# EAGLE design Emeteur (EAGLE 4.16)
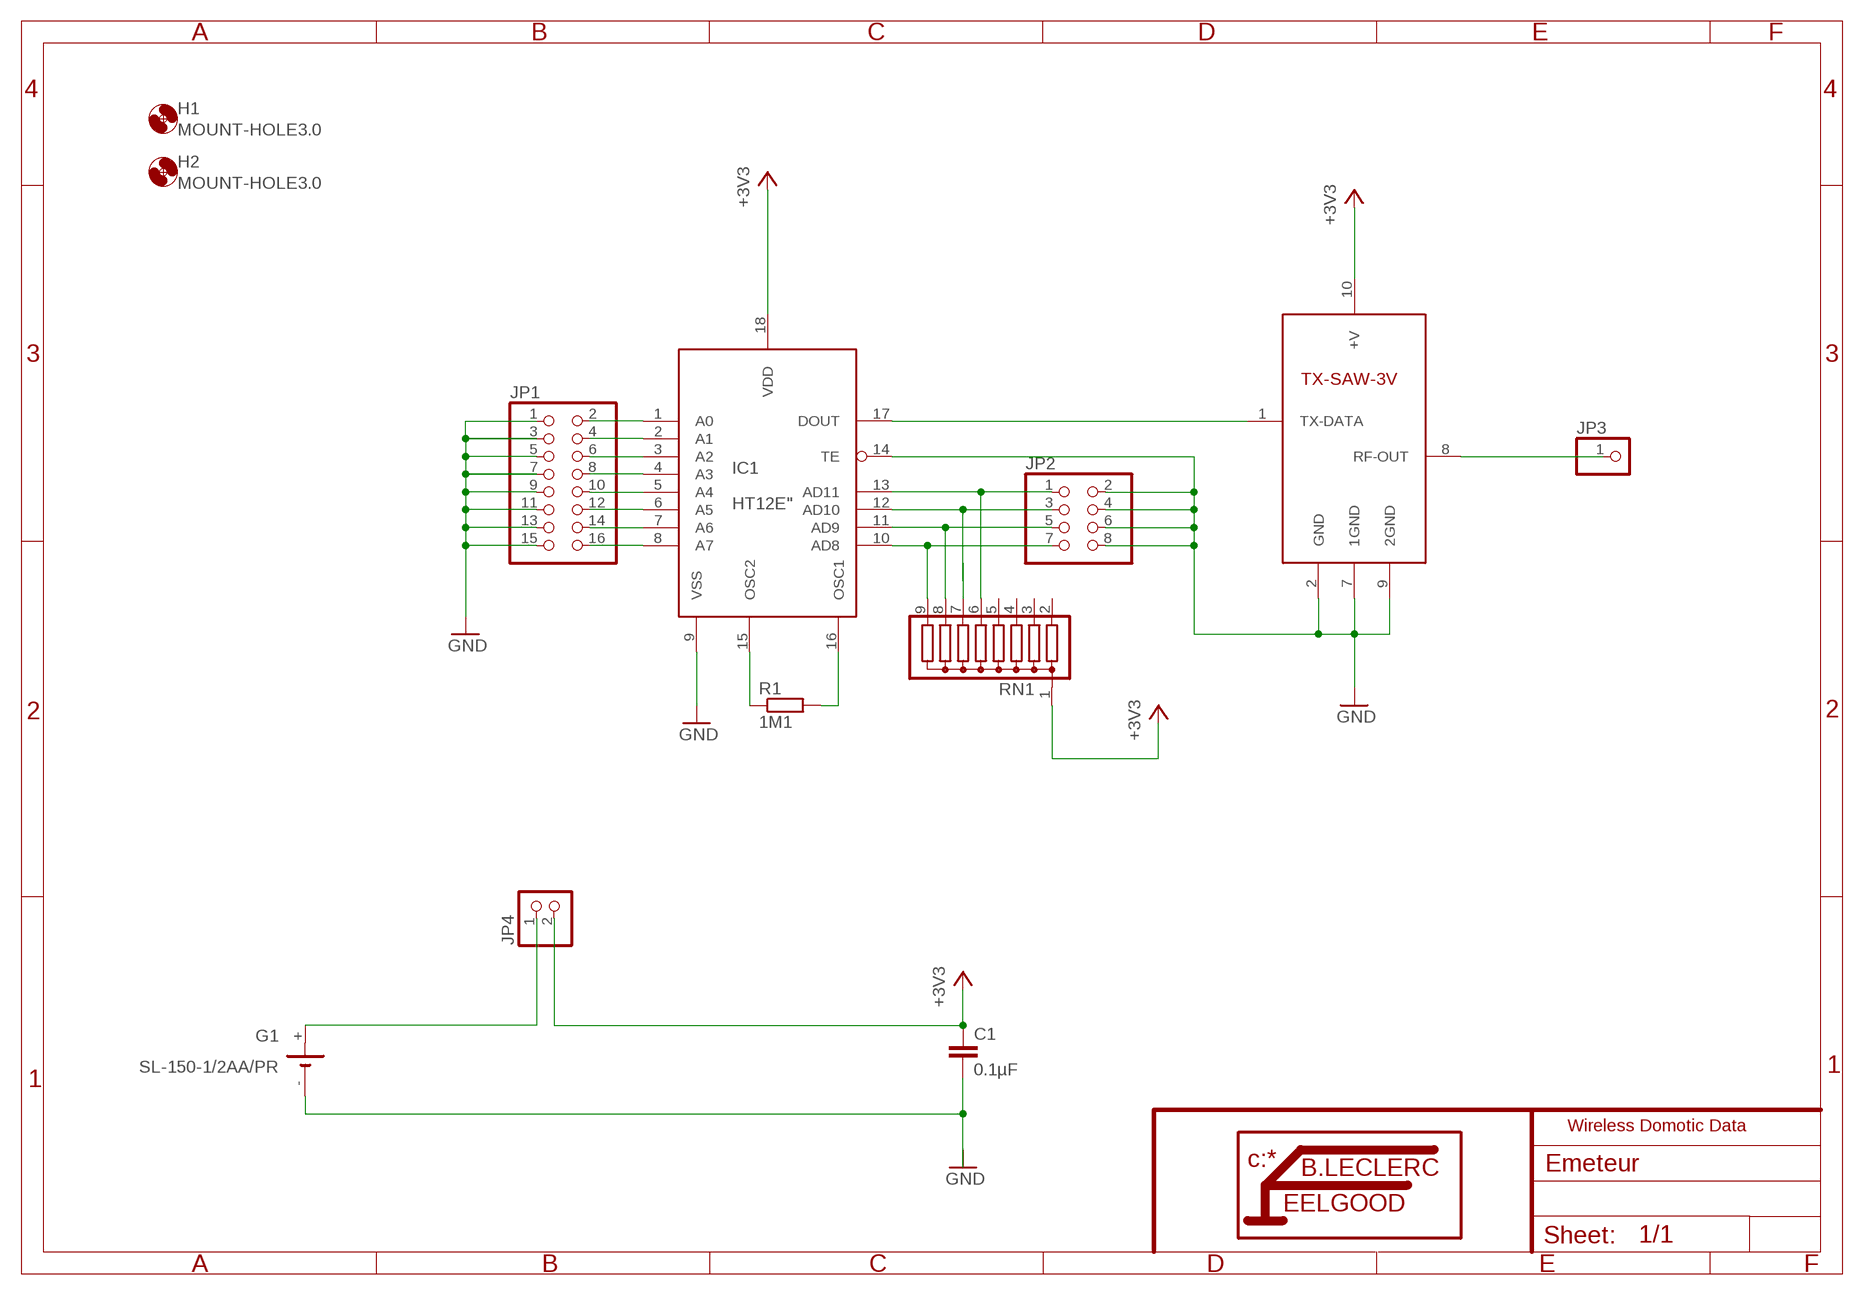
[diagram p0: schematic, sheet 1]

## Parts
C1  0.1µF  C-EU075-032X103  [C075-032X103]
G1  SL-150-1/2AA/PR  [SL-150-1/2AA/PR]
H1  MOUNT-HOLE3.0  [3,0]
H2  MOUNT-HOLE3.0  [3,0]
IC1  HT12E"  [18-DIP-A]
JP1  PINHD-2X8  [2X08]
JP2  PINHD-2X4  [2X04]
JP3  PINHD-1X1  [1X01]
JP4  PINHD-1X2  [1X02]
R1  1M1  R-EU_0207/10  [0207/10]
RN1  G08R  [SIL9]
TX-SAW1  AUREL_TX-SAW-3V  [AUREL_TX-SAW_3V]

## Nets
+3V3: C1.1 IC1.18(VDD) JP4.2 RN1.1 TX-SAW1.10(+V)
GND: C1.2 G1.- IC1.9(VSS) IC1.14(TE) JP1.1 JP1.3 JP1.5 JP1.7 JP1.9 JP1.11 JP1.13 JP1.15 JP2.2 JP2.4 JP2.6 JP2.8 TX-SAW1.2(GND) TX-SAW1.7(1GND) TX-SAW1.9(2GND)
N$1: JP3.1 TX-SAW1.8(RF-OUT)
N$2: IC1.13(AD11) JP2.1 RN1.6
N$3: IC1.17(DOUT) TX-SAW1.1(TX-DATA)
N$4: IC1.12(AD10) JP2.3 RN1.7
N$5: IC1.11(AD9) JP2.5 RN1.8
N$6: IC1.10(AD8) JP2.7 RN1.9
N$7: IC1.15(OSC2) R1.1
N$8: IC1.16(OSC1) R1.2
N$9: IC1.1(A0) JP1.2
N$10: IC1.2(A1) JP1.4
N$11: IC1.3(A2) JP1.6
N$12: IC1.4(A3) JP1.8
N$13: IC1.5(A4) JP1.10
N$14: IC1.6(A5) JP1.12
N$15: IC1.7(A6) JP1.14
N$16: IC1.8(A7) JP1.16
N$18: G1.+ JP4.1
Unconnected: RN1.2 RN1.3 RN1.4 RN1.5

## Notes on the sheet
- Wireless Domotic Data

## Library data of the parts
C1 = rcl:C-EU: CAPACITOR, European symbol
G1 = battery:SL-150-1/2AA/PR: LI BATTERY Sonnenschein
H1 H2 = holes:MOUNT-HOLE: MOUNTING HOLE with drill center marker
IC1 = holtek:HT12E: transmitter = encoder ic
JP1 = pinhead:PINHD-2X8: PIN HEADER
JP2 = pinhead:PINHD-2X4: PIN HEADER
JP3 = pinhead:PINHD-1X1: PIN HEADER
JP4 = pinhead:PINHD-1X2: PIN HEADER
R1 = rcl:R-EU_: RESISTOR, European symbol
RN1 = resistor-sil:G08R: SIL RESISTOR
TX-SAW1 = aurel:AUREL_TX-SAW-3V

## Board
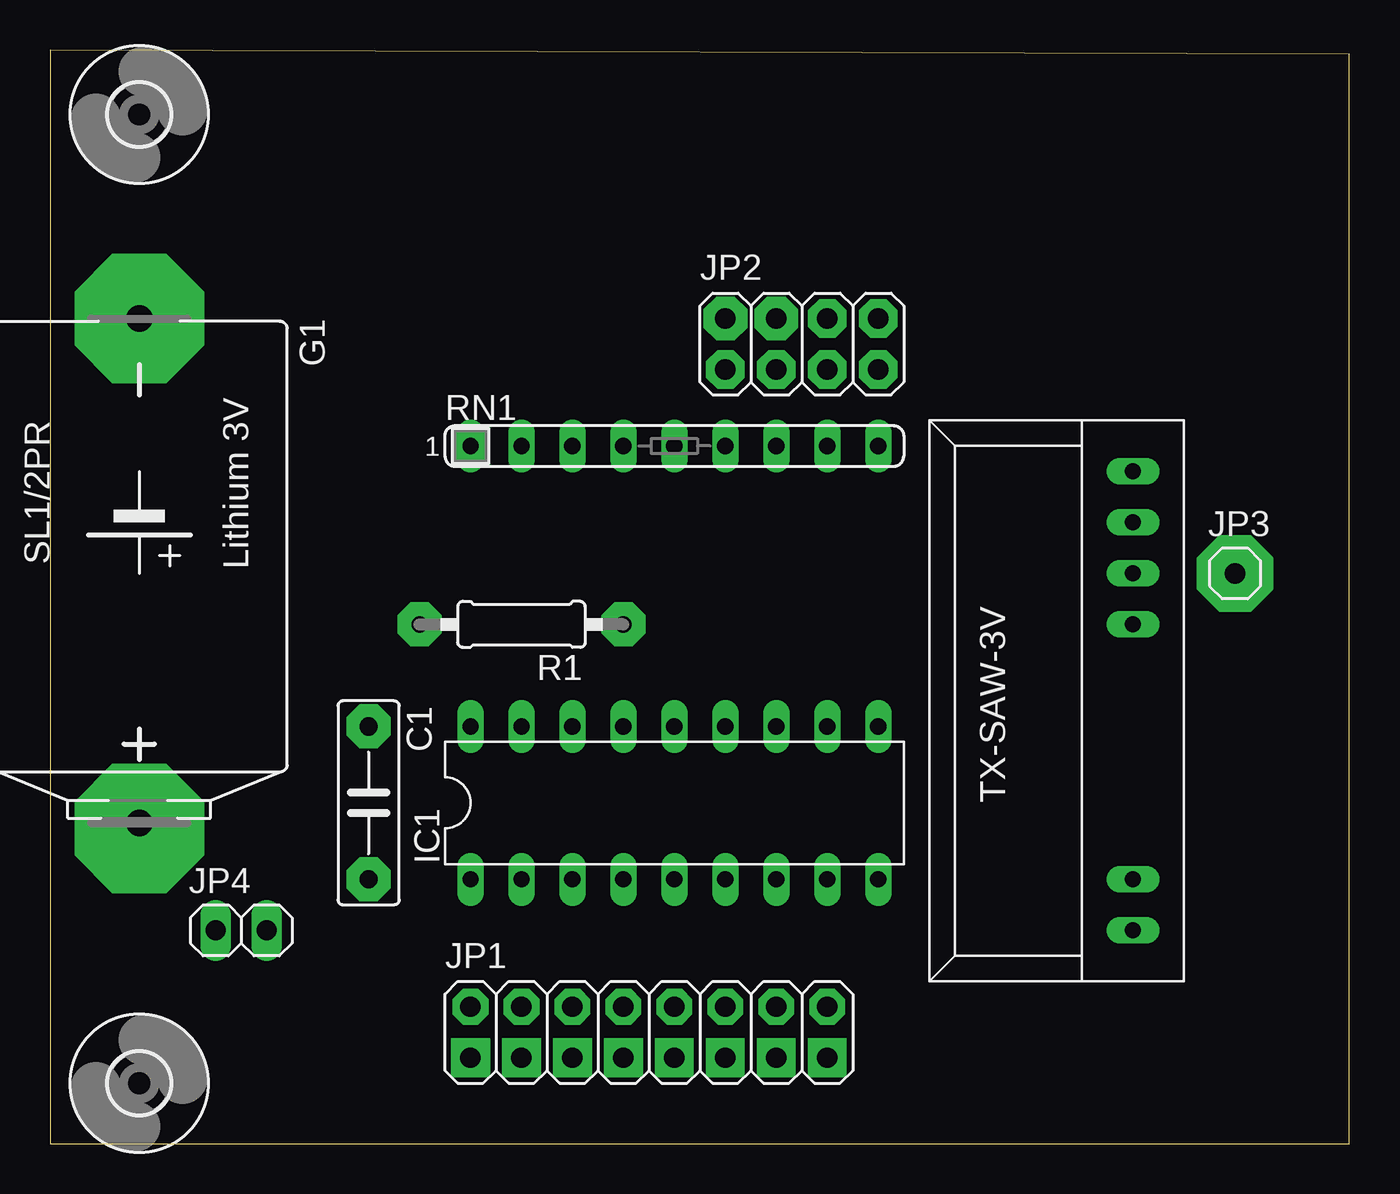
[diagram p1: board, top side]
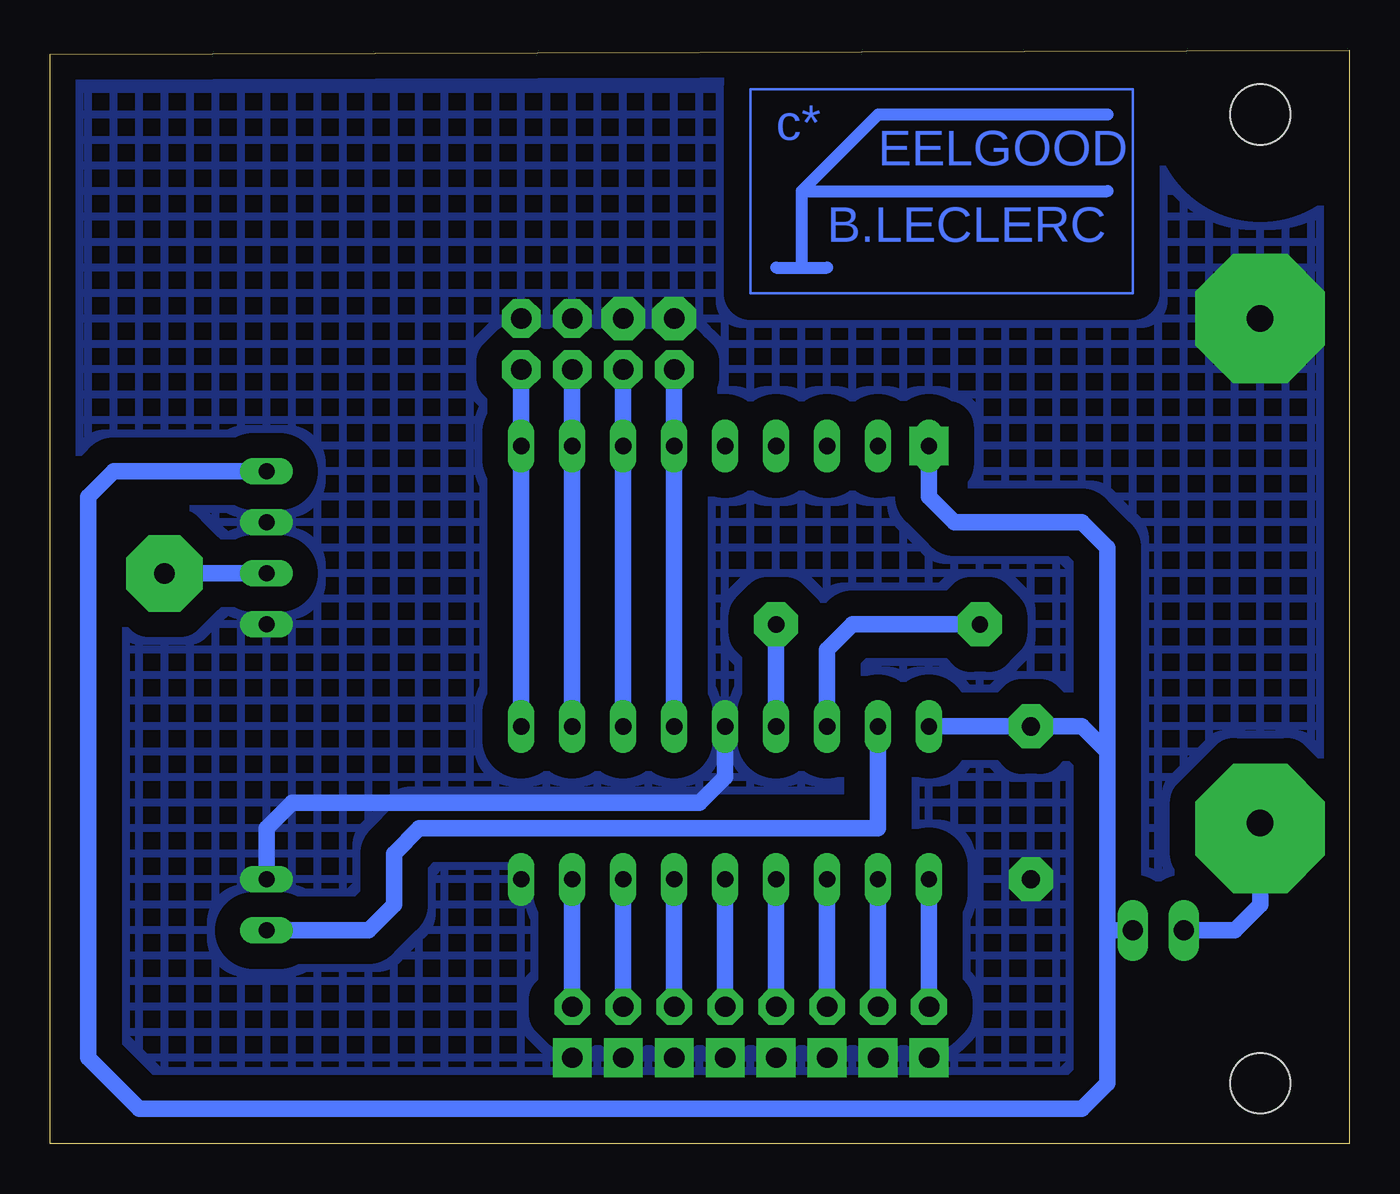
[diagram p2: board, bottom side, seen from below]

Size 64.75 x 54.48 mm. Coordinates in mm from the lower left corner, seen from the top.
Outline: 0,0 64.75,0 64.75,54.28 0,54.48 0,0
Copper layers (1*16): Top 0.035mm / dielectric 1.5mm / Bottom 0.035mm
Design rules "default": minimum track width 10mil, minimum drill 24mil, track to track 8mil, track to pad 8mil, pad to pad 8mil, via to via 8mil, smd to smd 8mil, copper to edge 40mil, drill to drill 8mil, minimum pad ring 10mil, minimum via ring 8mil, stop-mask expansion 4mil, vias tented up to drill 0mil, thermal gap 10mil

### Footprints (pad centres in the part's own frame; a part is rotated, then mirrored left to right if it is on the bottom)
C075-032X103 = drill 0.914 octagon: 1 -3.81,0; 2 3.81,0
SL-150-1/2AA/PR = drill 1.321 pad 3.15 octagon: + 12.446,0; - -12.7,0
3,0 = hole 3: 0,0
18-DIP-A = drill 0.813 long: 1 -10.16,-3.81; 2 -7.62,-3.81; 3 -5.08,-3.81; 4 -2.54,-3.81; 5 0,-3.81; 6 2.54,-3.81; 7 5.08,-3.81; 8 7.62,-3.81; 9 10.16,-3.81; 10 10.16,3.81; 11 7.62,3.81; 12 5.08,3.81; 13 2.54,3.81; 14 0,3.81; 15 -2.54,3.81; 16 -5.08,3.81; 17 -7.62,3.81; 18 -10.16,3.81
2X08 = drill 1.016 octagon: 1 -8.89,-1.27; 2 -8.89,1.27; 3 -6.35,-1.27; 4 -6.35,1.27; 5 -3.81,-1.27; 6 -3.81,1.27; 7 -1.27,-1.27; 8 -1.27,1.27; 9 1.27,-1.27; 10 1.27,1.27; 11 3.81,-1.27; 12 3.81,1.27; 13 6.35,-1.27; 14 6.35,1.27; 15 8.89,-1.27; 16 8.89,1.27
2X04 = drill 1.016 octagon: 1 -3.81,-1.27; 2 -3.81,1.27; 3 -1.27,-1.27; 4 -1.27,1.27; 5 1.27,-1.27; 6 1.27,1.27; 7 3.81,-1.27; 8 3.81,1.27
1X01 = drill 1.016 octagon: 1 0,0
1X02 = drill 1.016 long: 1 -1.27,0; 2 1.27,0
0207/10 = drill 0.813 octagon: 1 -5.08,0; 2 5.08,0
SIL9 = drill 0.813 long: 1 -10.16,0; 2 -7.62,0; 3 -5.08,0; 4 -2.54,0; 5 0,0; 6 2.54,0; 7 5.08,0; 8 7.62,0; 9 10.16,0
AUREL_TX-SAW_3V = drill 0.8 long: 1 -10.16,0; 2 -7.62,0; 7 5.08,0; 8 7.62,0; 9 10.16,0; 10 12.7,0

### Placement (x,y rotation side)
C1  15.87,16.98 270 top
G1  4.44,28.41 270 top
H1  4.44,3.01 0 top
H2  4.44,51.27 0 top
IC1  31.11,16.98 0 top
JP1  29.84,5.55 0 top
JP2  37.46,39.84 0 top
JP3  59.05,28.41 0 top
JP4  9.52,10.63 0 top
R1  23.49,25.87 180 top
RN1  31.11,34.76 0 top
TX-SAW1  53.97,20.79 90 top
U$2  [LITTFEEL]  27.3,39.84 0 bottom

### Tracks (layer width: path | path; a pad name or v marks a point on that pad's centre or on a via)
+3V3
  Bottom 0.813: 12.06,10.63 JP4.2 | 12.06,10.63 12.06,19.52 | 12.06,19.52 13.33,20.79 C1.1 IC1.18 | 12.06,19.52 12.06,29.68 13.33,30.95 19.68,30.95 20.95,32.22 RN1.1 | 12.06,10.63 12.06,3.01 13.33,1.74 60.32,1.74 62.86,4.28 62.86,32.22 61.59,33.49 TX-SAW1.10
GND  (via drill 0.6 pad 1.93, 0.6 pad 2.18, 0.6 pad 6.45)
  Bottom 0.813: IC1.14 31.11,18.25 32.38,16.98 52.7,16.98 53.97,15.71 TX-SAW1.2
  other vias: 15.87,13.17 33.65,41.11 36.19,41.11 38.73,41.11 41.27,41.11 4.44,41.11 20.95,4.28 23.49,4.28 26.03,4.28 28.57,4.28 31.11,4.28 33.65,4.28 36.19,4.28 38.73,4.28
  pour Bottom (isolate 1.27, no thermals, hatched): 0.63,53.81 64.13,53.81 64.13,0.47 0.63,0.47
N$1
  Bottom 0.813: TX-SAW1.8 JP3.1
N$2
  Bottom 0.813: JP2.1 RN1.6 IC1.13
N$3
  Bottom 0.813: IC1.17 23.49,15.71 46.35,15.71 47.62,14.44 47.62,11.9 48.89,10.63 TX-SAW1.1
N$4
  Bottom 0.813: JP2.3 RN1.7 IC1.12
N$5
  Bottom 0.813: JP2.5 RN1.8 IC1.11
N$6
  Bottom 0.813: IC1.10 RN1.9 JP2.7
N$7
  Bottom 0.813: IC1.15 R1.1
N$8
  Bottom 0.813: R1.2 24.76,25.87 26.03,24.6 IC1.16
N$9
  Bottom 0.813: JP1.2 IC1.1
N$10
  Bottom 0.813: JP1.4 IC1.2
N$11
  Bottom 0.813: JP1.6 IC1.3
N$12
  Bottom 0.813: JP1.8 IC1.4
N$13
  Bottom 0.813: JP1.10 IC1.5
N$14
  Bottom 0.813: JP1.12 IC1.6
N$15
  Bottom 0.813: JP1.14 IC1.7
N$16
  Bottom 0.813: JP1.16 IC1.8
N$17  (via drill 0.6 pad 2.18)
  other vias: 15.87,20.79
N$18
  Bottom 0.406: 4.44,15.71 G1.+
  Bottom 0.813: 4.44,15.71 4.44,11.9 5.71,10.63 JP4.1
N$20  (via drill 0.6 pad 2.18)
  other vias: 18.41,25.87
N$21  (via drill 0.6 pad 2.18)
  other vias: 28.57,25.87
N$22  (via drill 0.6 pad 3.81)
  other vias: 59.05,28.41
N$23  (via drill 0.6 pad 1.93)
  other vias: 36.19,38.57
N$24  (via drill 0.6 pad 1.93)
  other vias: 38.73,38.57
N$25  (via drill 0.6 pad 1.93)
  other vias: 41.27,38.57
N$28  (via drill 0.6 pad 1.93)
  other vias: 33.65,38.57
N$30  (via drill 0.6 pad 6.45)
  other vias: 4.44,15.71
N$35  (via drill 0.6 pad 1.93)
  other vias: 20.95,34.76
N$36  (via drill 0.6 pad 1.78)
  other vias: 33.65,6.82
N$37  (via drill 0.6 pad 1.78)
  other vias: 36.19,6.82
N$38  (via drill 0.6 pad 1.78)
  other vias: 38.73,6.82
N$39  (via drill 0.6 pad 1.78)
  other vias: 31.11,6.82
N$40  (via drill 0.6 pad 1.78)
  other vias: 28.57,6.82
N$41  (via drill 0.6 pad 1.78)
  other vias: 26.03,6.82
N$42  (via drill 0.6 pad 1.78)
  other vias: 23.49,6.82
N$43  (via drill 0.6 pad 1.78)
  other vias: 20.95,6.82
